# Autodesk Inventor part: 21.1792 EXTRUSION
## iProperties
Company: MiniTec Framing Systems, LLC
Created: 2007-05
Part Number: 21.1792 EXTRUSION
Material: Aluminum-6061
Document SubType Name: Modeling
Designer: Andy Moles
Density: 2.71 g/cm^3
Author: Andy Moles
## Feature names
1. Extrusion1
2. Hole1
3. Mirror1
4. Extrusion2
